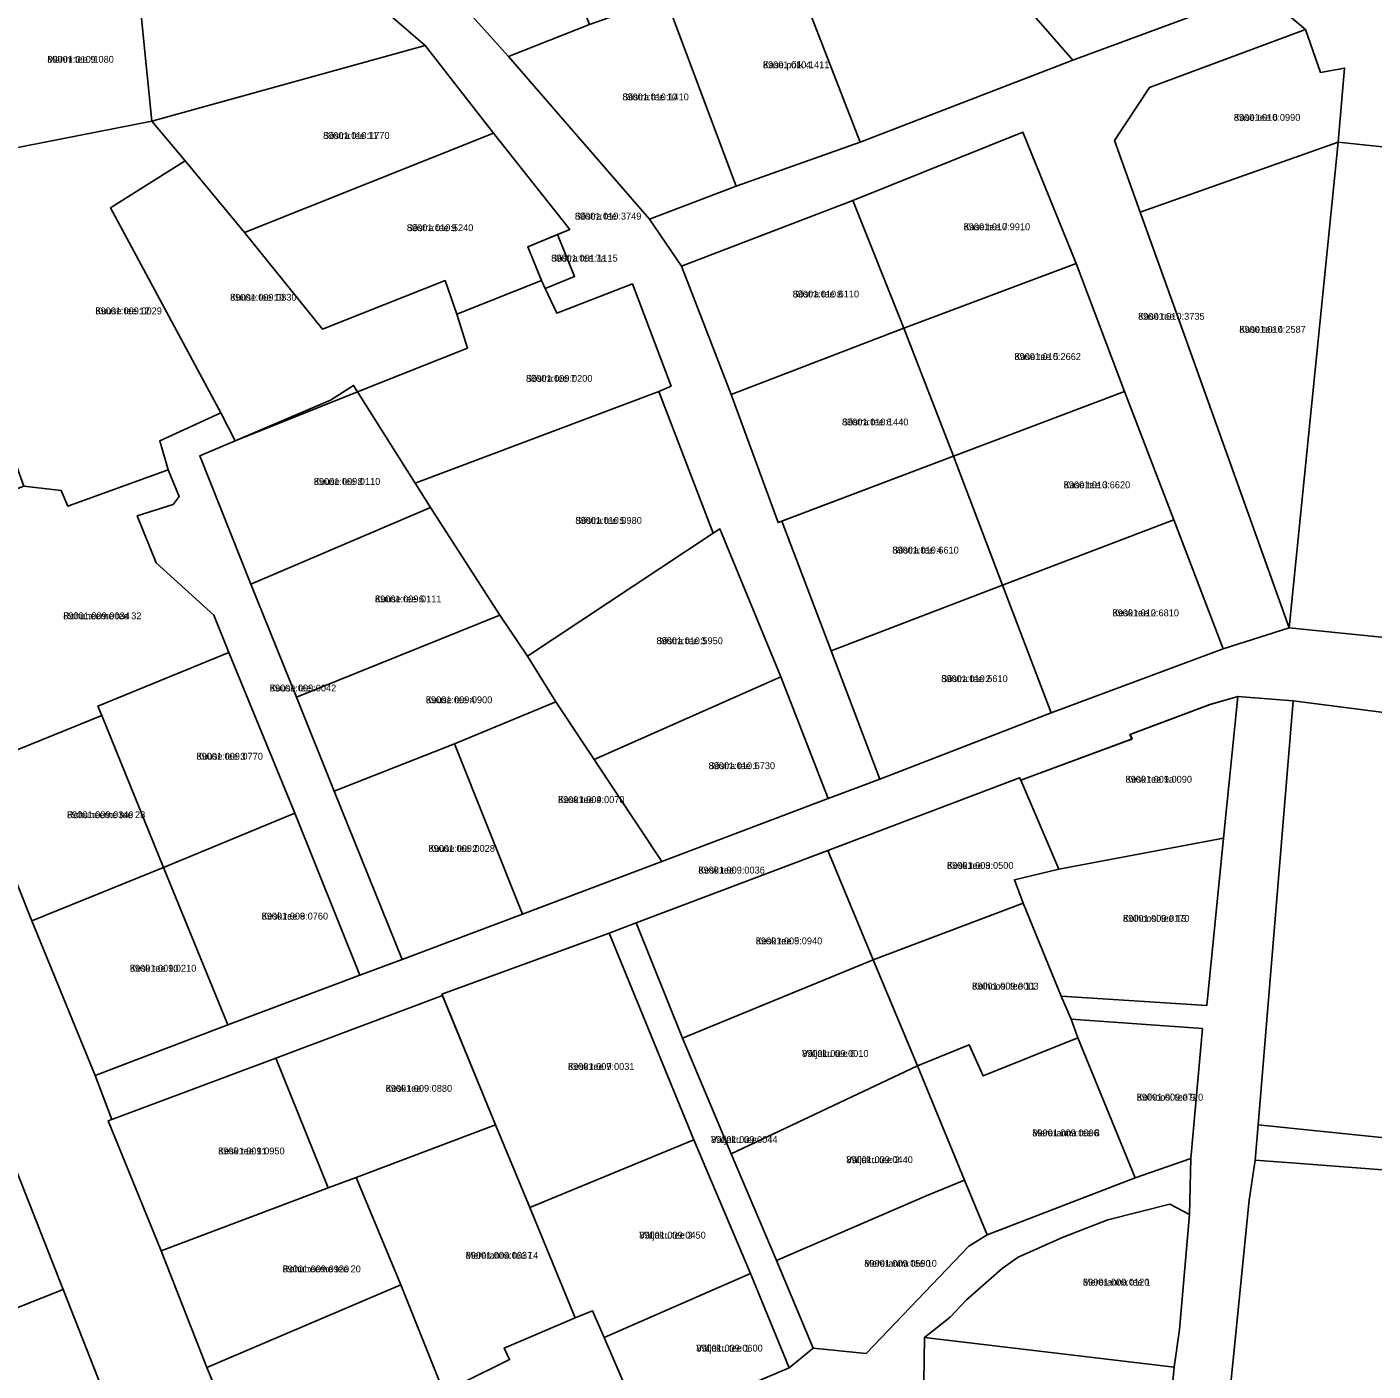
# Model space of a CAD drawing. Extents: x 526849 to 562296, y 6591741 to 6618546.
# Drawn here: x 546425 to 546718.7, y 6597379.4 to 6597672.6 of the extents above; entities that cross this region are included whole.
import ezdxf

# ---------------------------------------------------------------- set-up
doc = ezdxf.new("R2010")
doc.units = 0
for name, color, linetype in [('L_AADRESS', 7, 'Continuous'), ('PIIR', 7, 'Continuous'), ('TUNNUS', 7, 'Continuous')]:
    doc.layers.add(name, color=color, linetype=linetype)

msp = doc.modelspace()

# ---------------------------------------------------------------- linework, layer by layer
at = {"layer": 'PIIR'}
for points in [[(546619.76, 6597732.5), (546696.84, 6597721.18), (546693.97, 6597680.51), (546653.18, 6597665.39), (546621.6, 6597701.61), (546623.73, 6597702.62), (546591.75, 6597737.45)], [(546530.05, 6597666.19), (546498.43, 6597701.4), (546531.01, 6597714.44), (546547.71, 6597673.17)], [(546599.79, 6597504.32), (546589.45, 6597530.89), (546576.21, 6597563.15), (546574.74, 6597562.22), (546562.87, 6597593.08), (546565.53, 6597594.31), (546557.11, 6597616.57), (546540.61, 6597610.23), (546538.1, 6597615.57), (546544.5, 6597618.18), (546540.74, 6597627.36), (546543.42, 6597628.46), (546526.82, 6597649.44), (546511.91, 6597668.62), (546478, 6597697.82), (546498.43, 6597701.4), (546530.05, 6597666.19), (546560.81, 6597630.71), (546567.84, 6597620.42), (546578.63, 6597592.43), (546588.88, 6597564.53), (546589.71, 6597564.84), (546600.43, 6597536.54), (546611.09, 6597508.56)], [(546590.68, 6597689.16), (546621.6, 6597701.61), (546653.18, 6597665.39), (546606.81, 6597647.51)], [(546511.91, 6597668.62), (546452.28, 6597652.06), (546448.89, 6597685.38), (546478, 6597697.82)], [(546579.77, 6597637.88), (546564.32, 6597679.05), (546572.12, 6597682.45), (546590.68, 6597689.16), (546606.81, 6597647.51)], [(546407.03, 6597669.08), (546448.89, 6597685.38), (546452.28, 6597652.06), (546412.57, 6597644.27)], [(546547.71, 6597673.17), (546564.32, 6597679.05), (546579.77, 6597637.88), (546560.81, 6597630.71), (546530.05, 6597666.19)], [(546560.81, 6597630.71), (546579.77, 6597637.88), (546606.81, 6597647.51), (546653.18, 6597665.39), (546693.97, 6597680.51), (546703.92, 6597672.11), (546669.89, 6597659.4), (546662.28, 6597647.83), (546667.88, 6597632.21), (546677.44, 6597605.57), (546700.4, 6597541.56), (546685.95, 6597537), (546675.2, 6597565.11), (546664.48, 6597593.13), (546653.9, 6597621), (546642.3, 6597649.68), (546605.16, 6597634.81), (546567.84, 6597620.42)], [(546667.88, 6597632.21), (546662.28, 6597647.83), (546669.89, 6597659.4), (546703.92, 6597672.11), (546707.22, 6597662.71), (546712.45, 6597663.66), (546711.09, 6597647.48)], [(546511.91, 6597668.62), (546526.82, 6597649.44), (546472.5, 6597627.77), (546459.56, 6597643.45), (546452.28, 6597652.06)], [(546412.57, 6597644.27), (546452.28, 6597652.06), (546459.56, 6597643.45), (546443.23, 6597633.18), (546467.35, 6597588.46), (546453.99, 6597582.35), (546455.86, 6597576.02), (546433.95, 6597568.07), (546432.51, 6597571.53), (546424.32, 6597572.45), (546414.58, 6597599.38), (546418.97, 6597606.87), (546417.12, 6597612.57), (546418.29, 6597613.07), (546412.73, 6597642.76)], [(546543.42, 6597628.46), (546534.26, 6597624.7), (546537.29, 6597617.31), (546518.77, 6597609.99), (546516.23, 6597617.31), (546489.52, 6597606.73), (546472.5, 6597627.77), (546526.82, 6597649.44)], [(546642.3, 6597649.68), (546653.9, 6597621), (546616.32, 6597606.9), (546605.16, 6597634.81)], [(546667.88, 6597632.21), (546711.09, 6597647.48), (546707.96, 6597616.52), (546700.4, 6597541.56), (546677.44, 6597605.57)], [(546700.4, 6597541.56), (546707.96, 6597616.52), (546711.09, 6597647.48), (546724.9, 6597646.02), (546824.32, 6597635.5), (546813.16, 6597530.14)], [(546443.23, 6597633.18), (546459.56, 6597643.45), (546472.5, 6597627.77), (546489.52, 6597606.73), (546516.23, 6597617.31), (546518.77, 6597609.99), (546521.14, 6597602.57), (546497.14, 6597593.07), (546470.42, 6597582.37), (546467.35, 6597588.46)], [(546567.84, 6597620.42), (546605.16, 6597634.81), (546616.32, 6597606.9), (546578.63, 6597592.43)], [(546537.29, 6597617.31), (546534.26, 6597624.7), (546540.74, 6597627.36), (546544.5, 6597618.18), (546538.1, 6597615.57)], [(546616.32, 6597606.9), (546653.9, 6597621), (546664.48, 6597593.13), (546627.17, 6597578.98)], [(546497.14, 6597593.07), (546521.14, 6597602.57), (546518.77, 6597609.99), (546537.29, 6597617.31), (546538.1, 6597615.57), (546540.61, 6597610.23), (546557.11, 6597616.57), (546565.53, 6597594.31), (546562.87, 6597593.08), (546509.7, 6597573.13)], [(546616.32, 6597606.9), (546627.17, 6597578.98), (546588.88, 6597564.53), (546578.63, 6597592.43)], [(546491.22, 6597591.24), (546496.28, 6597594.42), (546497.14, 6597593.07), (546509.7, 6597573.13), (546513.04, 6597567.81), (546473.89, 6597551.05), (546462.72, 6597579.09), (546470.42, 6597582.37)], [(546574.74, 6597562.22), (546534.21, 6597535.39), (546528.21, 6597544.3), (546513.04, 6597567.81), (546509.7, 6597573.13), (546562.87, 6597593.08)], [(546627.17, 6597578.98), (546664.48, 6597593.13), (546675.2, 6597565.11), (546637.82, 6597550.88)], [(546506.88, 6597469.2), (546497.65, 6597465.79), (546483.48, 6597501.11), (546469.04, 6597536.21), (546465.77, 6597544.34), (546453.24, 6597555.72), (546449.09, 6597565.97), (546456.89, 6597568.45), (546458.24, 6597570.22), (546455.86, 6597576.02), (546453.99, 6597582.35), (546467.35, 6597588.46), (546470.42, 6597582.37), (546462.72, 6597579.09), (546473.89, 6597551.05), (546483.82, 6597526.41), (546492.08, 6597505.92)], [(546589.71, 6597564.84), (546627.17, 6597578.98), (546637.82, 6597550.88), (546600.43, 6597536.54)], [(546392.86, 6597560.66), (546395.34, 6597561.62), (546424.32, 6597572.45), (546432.51, 6597571.53), (546433.95, 6597568.07), (546455.86, 6597576.02), (546458.24, 6597570.22), (546456.89, 6597568.45), (546449.09, 6597565.97), (546453.24, 6597555.72), (546465.77, 6597544.34), (546469.04, 6597536.21), (546440.52, 6597524.49), (546441.38, 6597522.41), (546412.75, 6597510.84)], [(546473.89, 6597551.05), (546513.04, 6597567.81), (546528.21, 6597544.3), (546483.82, 6597526.41)], [(546637.82, 6597550.88), (546675.2, 6597565.11), (546685.95, 6597537), (546648.46, 6597523.03)], [(546589.45, 6597530.89), (546548.73, 6597512.84), (546540.41, 6597525.39), (546534.21, 6597535.39), (546574.74, 6597562.22), (546576.21, 6597563.15)], [(546611.09, 6597508.56), (546600.43, 6597536.54), (546637.82, 6597550.88), (546648.46, 6597523.03)], [(546483.82, 6597526.41), (546528.21, 6597544.3), (546534.21, 6597535.39), (546540.41, 6597525.39), (546518.26, 6597516.26), (546492.08, 6597505.92)], [(546441.38, 6597522.41), (546440.52, 6597524.49), (546469.04, 6597536.21), (546483.48, 6597501.11), (546454.8, 6597489.31)], [(546599.79, 6597504.32), (546563.51, 6597490.56), (546548.73, 6597512.84), (546589.45, 6597530.89)], [(546641.82, 6597508.3), (546666.05, 6597517.29), (546665.62, 6597518.3), (546683.07, 6597524.8), (546689.19, 6597526.6), (546686.08, 6597495.66), (546650.1, 6597488.94)], [(546676.52, 6597265.96), (546664.23, 6597256.73), (546670.26, 6597318.87), (546673, 6597356.56), (546675.3, 6597380.29), (546676.43, 6597388.53), (546678.65, 6597413.6), (546678.92, 6597425.79), (546681.44, 6597454.12), (546652.81, 6597456.17), (546650.66, 6597461.24), (546682.43, 6597459.2), (546686.08, 6597495.66), (546689.19, 6597526.6), (546701.21, 6597525.66), (546693.63, 6597433.12), (546692.94, 6597425.43), (546691.61, 6597416.72), (546677.67, 6597277.42)], [(546693.63, 6597433.12), (546701.21, 6597525.66), (546810.31, 6597511.59), (546801.15, 6597422.06)], [(546540.41, 6597525.39), (546563.51, 6597490.56), (546533.14, 6597479.09), (546518.26, 6597516.26)], [(546412.75, 6597510.84), (546441.38, 6597522.41), (546454.8, 6597489.31), (546426.07, 6597477.61)], [(546492.08, 6597505.92), (546518.26, 6597516.26), (546533.14, 6597479.09), (546506.88, 6597469.2)], [(546599.72, 6597492.97), (546641.58, 6597508.84), (546641.84, 6597508.3), (546650.1, 6597488.94), (546640.43, 6597486.59), (546642.34, 6597481.47), (546609.63, 6597469.11)], [(546497.65, 6597465.79), (546468.87, 6597454.95), (546454.8, 6597489.31), (546483.48, 6597501.11)], [(546682.43, 6597459.2), (546650.62, 6597461.23), (546642.34, 6597481.47), (546640.43, 6597486.59), (546650.1, 6597488.94), (546686.08, 6597495.66)], [(546599.72, 6597492.97), (546609.63, 6597469.11), (546568.05, 6597452.06), (546557.9, 6597477.23)], [(546454.8, 6597489.31), (546468.87, 6597454.95), (546439.94, 6597443.89), (546426.07, 6597477.61)], [(546642.34, 6597481.47), (546650.66, 6597461.24), (546652.81, 6597456.17), (546654.24, 6597452.09), (546633.65, 6597443.82), (546630.57, 6597450.62), (546619.28, 6597445.98), (546609.63, 6597469.11)], [(546591.27, 6597380.16), (546582.9, 6597400.7), (546570.53, 6597429.88), (546552, 6597474.98), (546557.9, 6597477.23), (546568.05, 6597452.06), (546578.63, 6597426.81), (546588.57, 6597403.57), (546596.51, 6597384.41)], [(546515.56, 6597461.64), (546552, 6597474.98), (546570.53, 6597429.88), (546534.74, 6597415.12), (546527.23, 6597433.11)], [(546568.05, 6597452.06), (546609.63, 6597469.11), (546619.28, 6597445.98), (546578.63, 6597426.81)], [(546527.23, 6597433.11), (546496.86, 6597421.68), (546490.7, 6597419.37), (546479.31, 6597447.7), (546515.69, 6597461.32)], [(546652.81, 6597456.17), (546681.44, 6597454.12), (546678.92, 6597425.79), (546666.76, 6597421.56), (546654.24, 6597452.09)], [(546630.57, 6597450.62), (546633.65, 6597443.82), (546654.24, 6597452.09), (546666.76, 6597421.56), (546634.49, 6597409.18), (546629.57, 6597421.07), (546619.28, 6597445.98)], [(546490.7, 6597419.37), (546454.27, 6597405.68), (546442.75, 6597434.03), (546443.57, 6597434.34), (546479.31, 6597447.7)], [(546619.28, 6597445.98), (546629.57, 6597421.07), (546621.52, 6597417.77), (546588.57, 6597403.57), (546578.63, 6597426.81)], [(546496.86, 6597421.68), (546527.23, 6597433.11), (546534.74, 6597415.12), (546544.61, 6597391.02), (546529.14, 6597384.45), (546530.31, 6597381.93), (546519.74, 6597376.71), (546531.46, 6597350.36), (546526.63, 6597348.68), (546516.48, 6597373.5), (546506.57, 6597398.26)], [(546692.94, 6597425.43), (546693.63, 6597433.12), (546801.15, 6597422.06), (546799.87, 6597418.32), (546797.47, 6597417.44), (546702.76, 6597424.7)], [(546534.74, 6597415.12), (546570.53, 6597429.88), (546582.9, 6597400.7), (546550.92, 6597386.77), (546548.43, 6597392.55), (546544.61, 6597391.02)], [(546421.29, 6597426.81), (546432.91, 6597397.19), (546395.83, 6597382.55), (546386.95, 6597412.31)], [(546692.94, 6597425.43), (546702.76, 6597424.7), (546797.47, 6597417.44), (546799.87, 6597418.32), (546803.01, 6597418.21), (546792.67, 6597336.4), (546784.04, 6597254.84), (546676.52, 6597265.96), (546677.67, 6597277.42), (546691.61, 6597416.72)], [(546464.29, 6597380.24), (546454.27, 6597405.68), (546490.7, 6597419.37), (546496.86, 6597421.68), (546506.57, 6597398.26)], [(546588.57, 6597403.57), (546621.52, 6597417.77), (546629.57, 6597421.07), (546634.49, 6597409.18), (546630.5, 6597406.64), (546608.1, 6597383.29), (546596.51, 6597384.41)], [(546626.45, 6597391.22), (546629.99, 6597395), (546637.74, 6597401.81), (546641.26, 6597404.26), (546651.05, 6597408.64), (546660.82, 6597412.44), (546674.37, 6597415.85), (546678.65, 6597413.6), (546676.43, 6597388.53), (546675.3, 6597380.29), (546620.82, 6597386.73)], [(546591.27, 6597380.16), (546559.57, 6597366.65), (546550.92, 6597386.77), (546582.9, 6597400.7)], [(546406.65, 6597353.75), (546395.83, 6597382.55), (546432.91, 6597397.19), (546443.93, 6597369.28), (546423.36, 6597360.27)], [(546464.29, 6597380.24), (546506.57, 6597398.26), (546516.48, 6597373.5), (546474.4, 6597355.96)], [(546544.61, 6597391.02), (546548.43, 6597392.55), (546550.92, 6597386.77), (546559.57, 6597366.65), (546561.03, 6597363.25), (546531.46, 6597350.36), (546519.74, 6597376.71), (546530.31, 6597381.93), (546529.14, 6597384.45)], [(546620.82, 6597386.73), (546675.3, 6597380.29), (546673, 6597356.56), (546649.58, 6597359.12), (546620.44, 6597362.42)]]:
    msp.add_lwpolyline(points, close=True, dxfattribs=at)
for points in [[(546518.84, 6597207.6), (546506.3, 6597229.96), (546505.57, 6597231.38), (546491.92, 6597259.35), (546488.56, 6597258.05), (546488.29, 6597257.91), (546478.8, 6597281.4), (546468.93, 6597305.22), (546465.16, 6597316.47), (546454.55, 6597343.58), (546443.93, 6597369.28), (546432.91, 6597397.19), (546421.29, 6597426.81), (546411.93, 6597436.48), (546410.43, 6597440), (546399.32, 6597466.03), (546388.52, 6597493.4), (546369.58, 6597537.93), (546367.53, 6597546.74), (546351.26, 6597587.7), (546333.49, 6597635.23), (546325.71, 6597651.46), (546311.88, 6597687.95)], [(546342.66, 6597681.78), (546354.23, 6597657.41), (546357.46, 6597649.31), (546392.86, 6597560.66), (546412.75, 6597510.84), (546426.07, 6597477.61), (546439.94, 6597443.89), (546443.57, 6597434.34), (546442.75, 6597434.03), (546454.27, 6597405.68), (546464.29, 6597380.24), (546474.4, 6597355.96), (546487.3, 6597326.14), (546494.39, 6597309.27), (546506.79, 6597278.69), (546516.4, 6597255.45), (546525.91, 6597233.41), (546537.23, 6597214.01)], [(546724.9, 6597646.02), (546711.09, 6597647.48), (546712.45, 6597663.66), (546707.22, 6597662.71), (546703.92, 6597672.11), (546693.97, 6597680.51)], [(546810.31, 6597511.59), (546701.21, 6597525.66), (546689.19, 6597526.6), (546683.15, 6597524.82), (546665.7, 6597518.32), (546666.09, 6597517.33), (546641.84, 6597508.3), (546641.58, 6597508.84), (546599.72, 6597492.97), (546557.9, 6597477.23), (546552, 6597474.98), (546515.56, 6597461.64), (546515.69, 6597461.32), (546479.31, 6597447.7), (546443.57, 6597434.34), (546439.94, 6597443.89), (546468.87, 6597454.95), (546497.65, 6597465.79), (546506.88, 6597469.2), (546533.14, 6597479.09), (546563.51, 6597490.56), (546599.79, 6597504.32), (546611.09, 6597508.56), (546648.46, 6597523.03), (546685.95, 6597537), (546700.4, 6597541.56), (546813.16, 6597530.14)], [(546559.57, 6597366.65), (546591.27, 6597380.16), (546596.51, 6597384.41), (546608.1, 6597383.29), (546630.5, 6597406.64), (546634.49, 6597409.18), (546666.76, 6597421.56), (546678.92, 6597425.79), (546678.65, 6597413.6), (546674.37, 6597415.85), (546660.82, 6597412.44), (546651.05, 6597408.64), (546641.26, 6597404.26), (546637.74, 6597401.81), (546629.99, 6597395), (546626.45, 6597391.22), (546620.82, 6597386.73), (546620.44, 6597362.42)]]:
    msp.add_lwpolyline(points, dxfattribs=at)

# ---------------------------------------------------------------- texts
at = {"layer": 'L_AADRESS'}
for s, p in [('Männi tee 9', (546429.48, 6597664.82)), ('Kase põik 4', (546585.57, 6597663.63)), ('Sõstra tee 10', (546554.91, 6597656.62)), ('Kase tee 6', (546688.31, 6597652.16)), ('Sõstra tee 11', (546489.62, 6597648.2)), ('Sõstra tee', (546544.55, 6597630.61)), ('Sõstra tee 9', (546507.9, 6597628.09)), ('Kase tee 7', (546629.36, 6597628.29)), ('Sõstra tee 7a', (546539.38, 6597621.45)), ('Kuuse tee 10', (546469.34, 6597612.91)), ('Sõstra tee 8', (546592.05, 6597613.62)), ('Kuuse tee 12', (546439.96, 6597609.95)), ('Kase tee', (546667.42, 6597608.76)), ('Kase tee 4', (546689.49, 6597605.92)), ('Kase tee 5', (546640.44, 6597599.99)), ('Sõstra tee 7', (546533.88, 6597595.22)), ('Sõstra tee 6', (546602.82, 6597585.71)), ('Kuuse tee 8', (546487.6, 6597572.74)), ('Kase tee 3', (546651.19, 6597572)), ('Sõstra tee 5', (546544.66, 6597564.24)), ('Sõstra tee 4', (546613.8, 6597557.76)), ('Kuuse tee 6', (546500.94, 6597547.11)), ('Rohuneeme tee 32', (546432.94, 6597543.43)), ('Kesk tee 2', (546661.83, 6597544.07)), ('Sõstra tee 3', (546562.34, 6597537.99)), ('Kuuse tee', (546477.99, 6597527.68)), ('Sõstra tee 2', (546624.47, 6597529.72)), ('Kuuse tee 4', (546512.04, 6597525.11)), ('Kuuse tee 3', (546462, 6597512.79)), ('Sõstra tee 1', (546573.72, 6597510.73)), ('Kesk tee 1a', (546664.67, 6597507.77)), ('Kesk tee 4', (546540.88, 6597503.34)), ('Rohuneeme tee 28', (546433.77, 6597500.04)), ('Kuuse tee 2', (546512.61, 6597492.69)), ('Kesk tee 3', (546625.73, 6597488.98)), ('Kesk tee', (546571.49, 6597487.95)), ('Kesk tee 8', (546476.22, 6597477.92)), ('Kolhoosi tee 13', (546664.12, 6597477.43)), ('Kesk tee 5', (546584.01, 6597472.51)), ('Kesk tee 10', (546447.47, 6597466.55)), ('Kolhoosi tee 11', (546631.2, 6597462.65)), ('Väljaku tee 6', (546594.11, 6597447.96)), ('Kesk tee 7', (546543.05, 6597445.12)), ('Kesk tee 9', (546503.27, 6597440.35)), ('Kolhoosi tee 9', (546667.12, 6597438.42)), ('Mereranna tee 8', (546644.33, 6597430.63)), ('Väljaku tee', (546574.25, 6597429.17)), ('Kesk tee 11', (546466.74, 6597426.69)), ('Väljaku tee 2', (546603.77, 6597424.78)), ('Väljaku tee 3', (546558.6, 6597408.32)), ('Mereranna tee 14', (546520.73, 6597403.93)), ('Rohuneeme tee 20', (546480.79, 6597400.96)), ('Mereranna tee 10', (546607.68, 6597402.18)), ('Mereranna tee 1', (546655.38, 6597398.07)), ('Väljaku tee 1', (546571.04, 6597383.67))]:
    msp.add_text(s, height=1.5, dxfattribs=at).set_placement(p)
at = {"layer": 'TUNNUS'}
for s, p in [('89001:010:1080', (546429.48, 6597664.82)), ('89001:010:1411', (546585.57, 6597663.63)), ('89001:010:1410', (546554.91, 6597656.62)), ('89001:010:0990', (546688.31, 6597652.16)), ('89001:010:1770', (546489.62, 6597648.2)), ('89001:010:3749', (546544.55, 6597630.61)), ('89001:010:5240', (546507.9, 6597628.09)), ('89001:010:9910', (546629.36, 6597628.29)), ('89001:001:1115', (546539.38, 6597621.45)), ('89001:009:0830', (546469.34, 6597612.91)), ('89001:010:6110', (546592.05, 6597613.62)), ('89001:009:0029', (546439.96, 6597609.95)), ('89001:010:3735', (546667.42, 6597608.76)), ('89001:010:2587', (546689.49, 6597605.92)), ('89001:010:2662', (546640.44, 6597599.99)), ('89001:009:0200', (546533.88, 6597595.22)), ('89001:010:1440', (546602.82, 6597585.71)), ('89001:009:0110', (546487.6, 6597572.74)), ('89001:010:6620', (546651.19, 6597572)), ('89001:010:0980', (546544.66, 6597564.24)), ('89001:010:6610', (546613.8, 6597557.76)), ('89001:009:0111', (546500.94, 6597547.11)), ('89001:009:0034', (546432.94, 6597543.43)), ('89001:010:6810', (546661.83, 6597544.07)), ('89001:010:5950', (546562.34, 6597537.99)), ('89001:009:0042', (546477.99, 6597527.68)), ('89001:010:5610', (546624.47, 6597529.72)), ('89001:009:0900', (546512.04, 6597525.11)), ('89001:009:0770', (546462, 6597512.79)), ('89001:010:6730', (546573.72, 6597510.73)), ('89001:009:0090', (546664.67, 6597507.77)), ('89001:009:0070', (546540.88, 6597503.34)), ('89001:009:0340', (546433.77, 6597500.04)), ('89001:009:0028', (546512.61, 6597492.69)), ('89001:009:0500', (546625.73, 6597488.98)), ('89001:009:0036', (546571.49, 6597487.95)), ('89001:009:0760', (546476.22, 6597477.92)), ('89001:009:0170', (546664.12, 6597477.43)), ('89001:009:0940', (546584.01, 6597472.51)), ('89001:009:0210', (546447.47, 6597466.55)), ('89001:009:0003', (546631.2, 6597462.65)), ('89001:009:0010', (546594.11, 6597447.96)), ('89001:009:0031', (546543.05, 6597445.12)), ('89001:009:0880', (546503.27, 6597440.35)), ('89001:009:0720', (546667.12, 6597438.42)), ('89001:009:0006', (546644.33, 6597430.63)), ('89001:009:0044', (546574.25, 6597429.17)), ('89001:009:0950', (546466.74, 6597426.69)), ('89001:009:0440', (546603.77, 6597424.78)), ('89001:009:0450', (546558.6, 6597408.32)), ('89001:009:0037', (546520.73, 6597403.93)), ('89001:009:0920', (546480.79, 6597400.96)), ('89001:009:0590', (546607.68, 6597402.18)), ('89001:009:0120', (546655.38, 6597398.07)), ('89001:009:0600', (546571.04, 6597383.67))]:
    msp.add_text(s, height=1.5, dxfattribs=at).set_placement(p)

doc.saveas('drawing.dxf')
